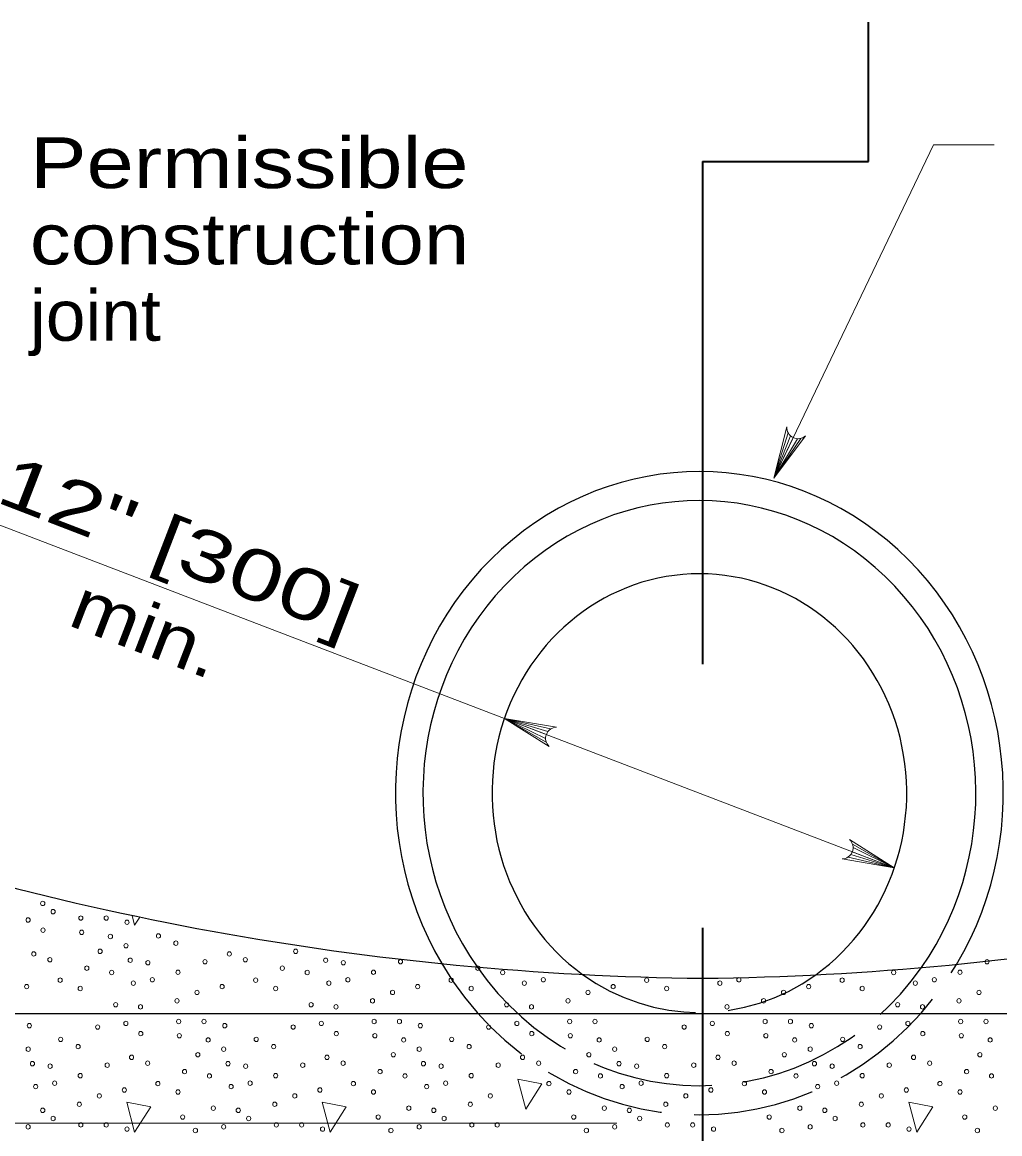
# Model space of a CAD drawing. Extents: x 1352.5 to 1386.5, y 735.9 to 779.9.
# Drawn here: x 1361.302 to 1364.306, y 770.968 to 774.385 of the extents above; entities that cross this region are included whole.
import ezdxf
from ezdxf.enums import TextEntityAlignment as Align

# ---------------------------------------------------------------- set-up
doc = ezdxf.new("R2010")
doc.units = 0
doc.header["$LTSCALE"] = 0.062
doc.linetypes.add('LONG_DASHED', pattern=[7.5, 6, -1.5])
doc.layers.add('1', color=7, linetype='Continuous', lineweight=13)

msp = doc.modelspace()

# ---------------------------------------------------------------- linework, layer by layer
at = {"layer": '1', "lineweight": 35}
for p, q in [((1363.90275, 773.957), (1363.90275, 774.3855)), ((1363.393, 773.957), (1363.90275, 773.957)), ((1363.393, 773.957), (1363.393, 772.41175)), ((1363.393, 771.60092), (1363.393, 770.5645))]:
    msp.add_line(p, q, dxfattribs=at)
at = {"layer": '1'}
for p, q in [((1363.65583, 773.12275), (1363.61175, 772.98392)), ((1363.66267, 773.114), (1363.61175, 772.98392)), ((1363.67125, 773.10825), (1363.61175, 772.98392)), ((1363.69483, 773.10592), (1363.61175, 772.98392)), ((1363.68408, 773.105), (1363.61175, 772.98392)), ((1361.01317, 772.92367), (1363.98158, 771.78567)), ((1362.91275, 772.19592), (1362.78392, 772.24483)), ((1362.9105, 772.18283), (1362.78392, 772.24483)), ((1362.91242, 772.17217), (1362.78392, 772.24483)), ((1362.91775, 772.20492), (1362.78392, 772.24483)), ((1362.92592, 772.2125), (1362.78392, 772.24483)), ((1363.85292, 771.83508), (1363.98158, 771.78567)), ((1363.85333, 771.85883), (1363.98158, 771.78567)), ((1363.85517, 771.84808), (1363.98158, 771.78567)), ((1363.83975, 771.8185), (1363.98158, 771.78567)), ((1363.84783, 771.82608), (1363.98158, 771.78567)), ((1363.12942, 771.00042), (1358.52633, 771.00042))]:
    msp.add_line(p, q, dxfattribs=at)
at = {"layer": '1', "lineweight": 25}
msp.add_line((1367.21625, 771.33708), (1359.56983, 771.33708), dxfattribs=at)
at = {"layer": '1'}
for points in [[(1363.61175, 772.98392), (1364.10233, 774.00808), (1364.28842, 774.00808)], [(1363.70925, 773.11392), (1363.61175, 772.98392), (1363.65175, 773.14133)], [(1362.9215, 772.1585), (1362.78392, 772.24483), (1362.94417, 772.21808)], [(1363.84433, 771.8725), (1363.98158, 771.78567), (1363.8215, 771.813)], [(1361.63967, 771.63925), (1361.64758, 771.60883), (1361.66375, 771.63408)]]:
    msp.add_lwpolyline(points, dxfattribs=at)
for points in [[(1362.82483, 771.13558), (1362.84917, 771.04342), (1362.89858, 771.12125)], [(1361.62333, 771.065), (1361.64758, 770.97283), (1361.69708, 771.05067)], [(1362.22408, 771.065), (1362.24842, 770.97283), (1362.29783, 771.05067)], [(1364.02642, 771.065), (1364.05067, 770.97283), (1364.10008, 771.05067)]]:
    msp.add_lwpolyline(points, close=True, dxfattribs=at)
for centre, start, end in [((1363.68604, 773.13925), 176.52786, 312.35399), ((1362.94485, 772.18373), 91.28673, 227.11286), ((1363.82086, 771.84736), 271.0866, 46.91273)]:
    msp.add_arc(centre, 0.03438, start, end, dxfattribs=at)
at = {"layer": '1', "lineweight": 25}
for centre, major_axis, start_param, end_param in [((1363.383, 772.01517), (0, 0.98868), 4.1510277, 8.4127939), ((1363.38303, 772.01517), (0, 0.89948), 4.0735039, 8.490283), ((1363.38303, 772.01517), (0, 0.67461), 3.7370766, 8.8263591), ((1363.49094, 781.45697), (0, -10.0114), 5.9523685, 6.2728294), ((1363.29509, 781.45697), (0, -10.0114), 0.0103559, 0.3308168)]:
    msp.add_ellipse(centre, major_axis=major_axis, ratio=0.944544, start_param=start_param, end_param=end_param, dxfattribs=at)
at = {"layer": '1'}
for centre in [(1361.36521, 771.67607), (1361.3203, 771.62513), (1361.3971, 771.65089), (1361.48226, 771.63112), (1361.56015, 771.63112), (1361.36601, 771.59391), (1361.48466, 771.58734), (1361.62418, 771.61824), (1361.57312, 771.57446), (1361.72071, 771.57616), (1361.77422, 771.55384), (1361.33762, 771.52093), (1361.54143, 771.52893), (1361.62093, 771.5461), (1361.93838, 771.52093), (1362.14219, 771.52893), (1361.38709, 771.50291), (1361.63395, 771.50148), (1361.68827, 771.49368), (1361.86374, 771.49692), (1361.98784, 771.50291), (1362.2347, 771.50148), (1362.28902, 771.49368), (1362.46449, 771.49692), (1364.26677, 771.49692), (1361.50063, 771.47715), (1361.57712, 771.46368), (1361.78073, 771.46448), (1362.10139, 771.47715), (1362.17788, 771.46368), (1362.38149, 771.46448), (1362.70214, 771.47715), (1362.77864, 771.46368), (1363.98016, 771.46368), (1364.18376, 771.46448), (1361.3157, 771.42043), (1361.41868, 771.4402), (1361.48035, 771.41445), (1361.64361, 771.43104), (1361.70203, 771.44137), (1361.91645, 771.42043), (1362.01943, 771.4402), (1362.08111, 771.41445), (1362.24437, 771.43104), (1362.30279, 771.44137), (1362.51721, 771.42043), (1362.62019, 771.4402), (1362.68187, 771.41445), (1362.84512, 771.43104), (1362.90355, 771.44137), (1363.11797, 771.42043), (1363.22095, 771.4402), (1363.28263, 771.41445), (1363.44588, 771.43104), (1363.50431, 771.44137), (1363.71873, 771.42043), (1363.82171, 771.4402), (1363.88338, 771.41445), (1364.04664, 771.43104), (1364.10506, 771.44137), (1361.83936, 771.40241), (1362.44011, 771.40241), (1363.04087, 771.40241), (1363.64163, 771.40241), (1364.24239, 771.40241), (1361.58904, 771.36468), (1361.66559, 771.35805), (1361.77778, 771.37665), (1362.1898, 771.36468), (1362.26634, 771.35805), (1362.37854, 771.37665), (1362.79056, 771.36468), (1362.8671, 771.35805), (1362.97929, 771.37665), (1363.46786, 771.35805), (1363.58005, 771.37665), (1363.99207, 771.36468), (1364.06862, 771.35805), (1364.18081, 771.37665), (1361.78263, 771.3131), (1361.86053, 771.3131), (1362.38339, 771.3131), (1362.46129, 771.3131), (1362.98415, 771.3131), (1363.06205, 771.3131), (1363.58491, 771.3131), (1363.66281, 771.3131), (1364.18567, 771.3131), (1364.26356, 771.3131), (1361.32381, 771.30023), (1361.53392, 771.29593), (1361.62068, 771.30712), (1361.92456, 771.30023), (1362.13468, 771.29593), (1362.22144, 771.30712), (1362.52532, 771.30023), (1362.73544, 771.29593), (1362.8222, 771.30712), (1363.33619, 771.29593), (1363.42295, 771.30712), (1363.72684, 771.30023), (1363.93695, 771.29593), (1364.02371, 771.30712), (1361.42033, 771.25814), (1361.66639, 771.2759), (1361.78504, 771.26932), (1361.8735, 771.25645), (1362.02109, 771.25814), (1362.26715, 771.2759), (1362.3858, 771.26932), (1362.47426, 771.25645), (1362.62184, 771.25814), (1362.8679, 771.2759), (1362.98655, 771.26932), (1363.07501, 771.25645), (1363.2226, 771.25814), (1363.46866, 771.2759), (1363.58731, 771.26932), (1363.67577, 771.25645), (1363.82336, 771.25814), (1364.06942, 771.2759), (1364.18807, 771.26932), (1364.27653, 771.25645), (1361.32055, 771.22809), (1361.47384, 771.23583), (1361.84181, 771.21092), (1361.92131, 771.22809), (1362.0746, 771.23583), (1362.44257, 771.21092), (1362.52207, 771.22809), (1362.67536, 771.23583), (1363.04332, 771.21092), (1363.12283, 771.22809), (1363.27612, 771.23583), (1363.64408, 771.21092), (1363.72358, 771.22809), (1363.87688, 771.23583), (1364.24484, 771.21092), (1361.33357, 771.18346), (1361.38789, 771.17567), (1361.56336, 771.1789), (1361.638, 771.20291), (1361.68746, 771.18489), (1361.93433, 771.18346), (1361.98864, 771.17567), (1362.16412, 771.1789), (1362.23876, 771.20291), (1362.28822, 771.18489), (1362.53508, 771.18346), (1362.5894, 771.17567), (1362.76487, 771.1789), (1362.83952, 771.20291), (1362.88898, 771.18489), (1363.13584, 771.18346), (1363.19016, 771.17567), (1363.36563, 771.1789), (1363.44028, 771.20291), (1363.48974, 771.18489), (1363.7366, 771.18346), (1363.79092, 771.17567), (1363.96639, 771.1789), (1364.04103, 771.20291), (1364.0905, 771.18489), (1361.48035, 771.14646), (1361.80101, 771.15913), (1361.8775, 771.14567), (1362.08111, 771.14646), (1362.40177, 771.15913), (1362.47826, 771.14567), (1362.68187, 771.14646), (1363.00252, 771.15913), (1363.07902, 771.14567), (1363.28263, 771.14646), (1363.60328, 771.15913), (1363.67978, 771.14567), (1363.88338, 771.14646), (1364.20404, 771.15913), (1364.28054, 771.14567), (1361.34323, 771.11302), (1361.40165, 771.12336), (1361.71905, 771.12219), (1361.94399, 771.11302), (1362.00241, 771.12336), (1362.31981, 771.12219), (1362.54475, 771.11302), (1362.60317, 771.12336), (1362.92057, 771.12219), (1363.1455, 771.11302), (1363.20393, 771.12336), (1363.52133, 771.12219), (1363.74626, 771.11302), (1363.80469, 771.12336), (1364.12209, 771.12219), (1361.53898, 771.0844), (1361.61607, 771.10242), (1361.78073, 771.09643), (1362.13973, 771.0844), (1362.21683, 771.10242), (1362.38149, 771.09643), (1362.74049, 771.0844), (1362.98225, 771.09643), (1363.34125, 771.0844), (1363.41835, 771.10242), (1363.58301, 771.09643), (1363.94201, 771.0844), (1364.01911, 771.10242), (1364.18376, 771.09643), (1361.36521, 771.04004), (1361.4774, 771.05864), (1361.88942, 771.04666), (1361.96597, 771.04004), (1362.07816, 771.05864), (1362.49018, 771.04666), (1362.56672, 771.04004), (1362.67892, 771.05864), (1363.09093, 771.04666), (1363.16748, 771.04004), (1363.27967, 771.05864), (1363.69169, 771.04666), (1363.76824, 771.04004), (1363.88043, 771.05864), (1364.29245, 771.04666), (1361.3971, 771.01486), (1361.79535, 771.01915), (1361.99786, 771.01486), (1362.39611, 771.01915), (1362.59861, 771.01486), (1362.99687, 771.01915), (1363.19937, 771.01486), (1363.59762, 771.01915), (1363.80013, 771.01486), (1364.19838, 771.01915), (1361.3203, 770.9891), (1361.48226, 770.99509), (1361.56015, 770.99509), (1361.62418, 770.98221), (1361.8343, 770.97792), (1361.92106, 770.9891), (1362.08301, 770.99509), (1362.16091, 770.99509), (1362.22494, 770.98221), (1362.43506, 770.97792), (1362.52182, 770.9891), (1362.68377, 770.99509), (1362.76167, 770.99509), (1363.03582, 770.97792), (1363.12257, 770.9891), (1363.28453, 770.99509), (1363.36243, 770.99509), (1363.42646, 770.98221), (1363.63657, 770.97792), (1363.72333, 770.9891), (1363.88529, 770.99509), (1363.96319, 770.99509), (1364.02722, 770.98221), (1364.23733, 770.97792)]:
    msp.add_ellipse(centre, major_axis=(0, 0.0068), ratio=0.944544, dxfattribs=at)
at = {"layer": '1', "linetype": 'LONG_DASHED', "lineweight": 25}
for centre, major_axis, start_param, end_param in [((1363.383, 772.01517), (0, 0.98868), 2.1296086, 4.1510277), ((1363.38303, 772.01517), (0, 0.89948), 2.2070977, 4.073504), ((1363.38303, 772.01517), (0, 0.67461), 2.5431737, 3.7370766)]:
    msp.add_ellipse(centre, major_axis=major_axis, ratio=0.944544, start_param=start_param, end_param=end_param, dxfattribs=at)

# ---------------------------------------------------------------- texts
at = {"layer": '1'}
for s, width, p in [('Permissible', 1.25, (1361.32592, 773.8755)), ('construction', 1.2, (1361.32592, 773.64083)), ('joint', 1.05, (1361.32592, 773.40617))]:
    msp.add_text(s, height=0.156, dxfattribs=dict(at, width=width)).set_placement(p)
for s, width, p in [('12" [300]', 1.4, (1361.75656, 772.70427)), ('min.', 1.2, (1361.65806, 772.4486))]:
    msp.add_text(s, height=0.156, rotation=338.942, dxfattribs=dict(at, width=width)).set_placement(p, align=Align.CENTER)

doc.saveas('drawing.dxf')
